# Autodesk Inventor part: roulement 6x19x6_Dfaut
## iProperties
Created: 2006-03
Part Number: roulement 6x19x6_Dfaut
Document SubType Name: Modeling
Designer: Flavien MARTY
Author: Flavien MARTY
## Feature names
1. Base1
